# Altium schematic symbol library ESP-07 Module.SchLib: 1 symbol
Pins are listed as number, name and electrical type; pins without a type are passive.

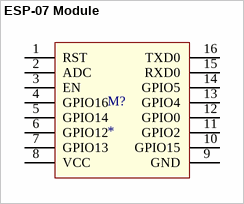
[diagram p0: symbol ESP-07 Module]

## ESP-07 Module
designator M?
ESP-07 Module
footprint ESP-07 Module
pins: 1 RST, 2 ADC, 3 EN, 4 GPIO16, 5 GPIO14, 6 GPIO12, 7 GPIO13, 8 VCC, 9 GND, 10 GPIO15, 11 GPIO2, 12 GPIO0, 13 GPIO4, 14 GPIO5, 15 RXD0, 16 TXD0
